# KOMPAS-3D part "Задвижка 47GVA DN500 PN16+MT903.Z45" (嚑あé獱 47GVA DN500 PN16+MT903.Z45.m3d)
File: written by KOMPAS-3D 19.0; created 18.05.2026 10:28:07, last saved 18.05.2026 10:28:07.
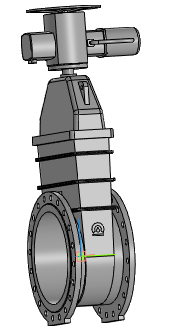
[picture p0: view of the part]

Document properties: Автор: Энергия; Полное имя файла: ..\Задвижка 47GVA DN50_DN1000+MT903.Z\Задвижка 47GVA DN500 PN16+MT903.Z45.a3d

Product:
- Part/product: Задвижка 47GVA DN500 PN16+MT903.Z45
    Масса: 923.441
  - Body: Электропривод MT903.Z45-60
      Масса: 170.293
  - Body: Задвижка 47GVA DN500 PN16 без исполнительного механизма
      Масса: 753.149

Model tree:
1. Операция без истории:1
2. Операция без истории:2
